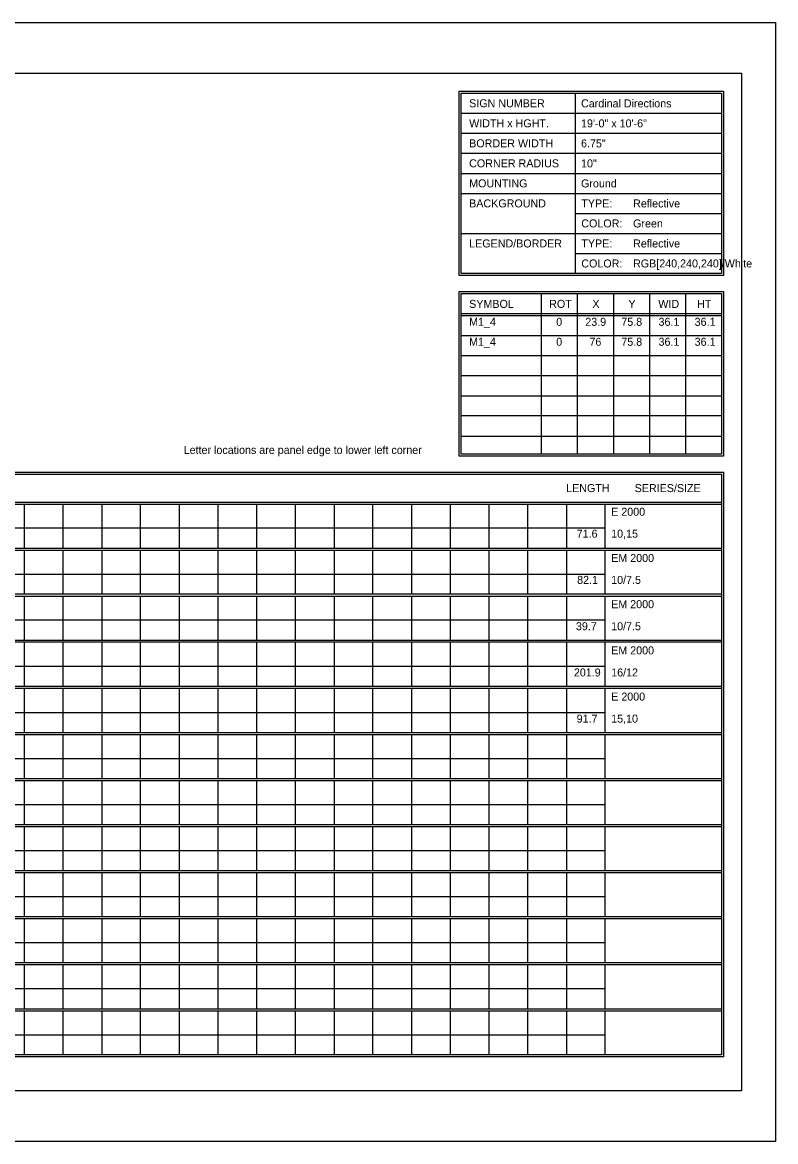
# Model space of a CAD drawing. Extents: x 1806251 to 1809821, y 414895 to 422886.
# Drawn here: x 1809679.34 to 1809684.89, y 414975.97 to 414984.23 of the extents above; entities that cross this region are included whole.
import ezdxf

# ---------------------------------------------------------------- set-up
doc = ezdxf.new("R2010")
doc.units = 0
doc.layers.add('GSSHT', color=7, linetype='Continuous')

msp = doc.modelspace()

# ---------------------------------------------------------------- linework, layer by layer
at = {"layer": 'GSSHT'}
for p, q in [((1809672.1343, 414984.2267), (1809684.8885, 414984.2267)), ((1809684.8885, 414984.2267), (1809684.8885, 414975.9729)), ((1809683.412, 414983.704), (1809683.412, 414982.3751)), ((1809682.5704, 414983.5563), (1809684.4899, 414983.5563)), ((1809682.5704, 414983.4087), (1809684.4899, 414983.4087)), ((1809682.5704, 414983.261), (1809684.4899, 414983.261)), ((1809682.5704, 414983.1134), (1809684.4899, 414983.1134)), ((1809682.5704, 414982.9657), (1809684.4899, 414982.9657)), ((1809683.412, 414982.8181), (1809684.4899, 414982.8181)), ((1809682.5704, 414982.6704), (1809684.4899, 414982.6704)), ((1809683.412, 414982.5227), (1809684.4899, 414982.5227)), ((1809683.161, 414982.2274), (1809683.161, 414981.0433)), ((1809683.4268, 414982.2274), (1809683.4268, 414981.0433)), ((1809683.6926, 414982.2274), (1809683.6926, 414981.0433)), ((1809683.9583, 414982.2274), (1809683.9583, 414981.0433)), ((1809684.2241, 414982.2274), (1809684.2241, 414981.0433)), ((1809682.5704, 414982.0798), (1809684.4899, 414982.0798)), ((1809682.5704, 414982.065), (1809684.4899, 414982.065)), ((1809682.5704, 414981.9174), (1809684.4899, 414981.9174)), ((1809682.5704, 414981.7697), (1809684.4899, 414981.7697)), ((1809682.5704, 414981.6221), (1809684.4899, 414981.6221)), ((1809682.5704, 414981.4715), (1809684.4899, 414981.4715)), ((1809682.5704, 414981.3268), (1809684.4899, 414981.3268)), ((1809682.5704, 414981.1762), (1809684.4899, 414981.1762)), ((1809672.781, 414980.6889), (1809684.4899, 414980.6889)), ((1809672.781, 414980.6741), (1809684.4899, 414980.6741)), ((1809679.3486, 414980.6741), (1809679.3486, 414980.3493)), ((1809679.6351, 414980.6741), (1809679.6351, 414980.3493)), ((1809679.9215, 414980.6741), (1809679.9215, 414980.3493)), ((1809680.205, 414980.6741), (1809680.205, 414980.3493)), ((1809680.4914, 414980.6741), (1809680.4914, 414980.3493)), ((1809680.7779, 414980.6741), (1809680.7779, 414980.3493)), ((1809681.0614, 414980.6741), (1809681.0614, 414980.3493)), ((1809681.3478, 414980.6741), (1809681.3478, 414980.3493)), ((1809681.6343, 414980.6741), (1809681.6343, 414980.3493)), ((1809681.9178, 414980.6741), (1809681.9178, 414980.3493)), ((1809682.2042, 414980.6741), (1809682.2042, 414980.3493)), ((1809682.4907, 414980.6741), (1809682.4907, 414980.3493)), ((1809682.7742, 414980.6741), (1809682.7742, 414980.3493)), ((1809683.0606, 414980.6741), (1809683.0606, 414980.3493)), ((1809683.347, 414980.6741), (1809683.347, 414980.3493)), ((1809683.6305, 414980.6741), (1809683.6305, 414980.3493)), ((1809672.781, 414980.4999), (1809683.6305, 414980.4999)), ((1809672.781, 414980.3493), (1809684.4899, 414980.3493)), ((1809672.781, 414980.3345), (1809684.4899, 414980.3345)), ((1809679.3486, 414980.3345), (1809679.3486, 414980.0127)), ((1809679.6351, 414980.3345), (1809679.6351, 414980.0127)), ((1809679.9215, 414980.3345), (1809679.9215, 414980.0127)), ((1809680.205, 414980.3345), (1809680.205, 414980.0127)), ((1809680.4914, 414980.3345), (1809680.4914, 414980.0127)), ((1809680.7779, 414980.3345), (1809680.7779, 414980.0127)), ((1809681.0614, 414980.3345), (1809681.0614, 414980.0127)), ((1809681.3478, 414980.3345), (1809681.3478, 414980.0127)), ((1809681.6343, 414980.3345), (1809681.6343, 414980.0127)), ((1809681.9178, 414980.3345), (1809681.9178, 414980.0127)), ((1809682.2042, 414980.3345), (1809682.2042, 414980.0127)), ((1809682.4907, 414980.3345), (1809682.4907, 414980.0127)), ((1809682.7742, 414980.3345), (1809682.7742, 414980.0127)), ((1809683.0606, 414980.3345), (1809683.0606, 414980.0127)), ((1809683.347, 414980.3345), (1809683.347, 414980.0127)), ((1809683.6305, 414980.3345), (1809683.6305, 414980.0127)), ((1809672.781, 414980.1574), (1809683.6305, 414980.1574)), ((1809672.781, 414980.0127), (1809684.4899, 414980.0127)), ((1809672.781, 414979.9949), (1809684.4899, 414979.9949)), ((1809679.3486, 414979.9949), (1809679.3486, 414979.6701)), ((1809679.6351, 414979.9949), (1809679.6351, 414979.6701)), ((1809679.9215, 414979.9949), (1809679.9215, 414979.6701)), ((1809680.205, 414979.9949), (1809680.205, 414979.6701)), ((1809680.4914, 414979.9949), (1809680.4914, 414979.6701)), ((1809680.7779, 414979.9949), (1809680.7779, 414979.6701)), ((1809681.0614, 414979.9949), (1809681.0614, 414979.6701)), ((1809681.3478, 414979.9949), (1809681.3478, 414979.6701)), ((1809681.6343, 414979.9949), (1809681.6343, 414979.6701)), ((1809681.9178, 414979.9949), (1809681.9178, 414979.6701)), ((1809682.2042, 414979.9949), (1809682.2042, 414979.6701)), ((1809682.4907, 414979.9949), (1809682.4907, 414979.6701)), ((1809682.7742, 414979.9949), (1809682.7742, 414979.6701)), ((1809683.0606, 414979.9949), (1809683.0606, 414979.6701)), ((1809683.347, 414979.9949), (1809683.347, 414979.6701)), ((1809683.6305, 414979.9949), (1809683.6305, 414979.6701)), ((1809672.781, 414979.8207), (1809683.6305, 414979.8207)), ((1809672.781, 414979.6701), (1809684.4899, 414979.6701)), ((1809672.781, 414979.6583), (1809684.4899, 414979.6583)), ((1809679.3486, 414979.6583), (1809679.3486, 414979.3305)), ((1809679.6351, 414979.6583), (1809679.6351, 414979.3305)), ((1809679.9215, 414979.6583), (1809679.9215, 414979.3305)), ((1809680.205, 414979.6583), (1809680.205, 414979.3305)), ((1809680.4914, 414979.6583), (1809680.4914, 414979.3305)), ((1809680.7779, 414979.6583), (1809680.7779, 414979.3305)), ((1809681.0614, 414979.6583), (1809681.0614, 414979.3305)), ((1809681.3478, 414979.6583), (1809681.3478, 414979.3305)), ((1809681.6343, 414979.6583), (1809681.6343, 414979.3305)), ((1809681.9178, 414979.6583), (1809681.9178, 414979.3305)), ((1809682.2042, 414979.6583), (1809682.2042, 414979.3305)), ((1809682.4907, 414979.6583), (1809682.4907, 414979.3305)), ((1809682.7742, 414979.6583), (1809682.7742, 414979.3305)), ((1809683.0606, 414979.6583), (1809683.0606, 414979.3305)), ((1809683.347, 414979.6583), (1809683.347, 414979.3305)), ((1809683.6305, 414979.6583), (1809683.6305, 414979.3305)), ((1809672.781, 414979.4782), (1809683.6305, 414979.4782)), ((1809672.781, 414979.3305), (1809684.4899, 414979.3305)), ((1809672.781, 414979.3157), (1809684.4899, 414979.3157)), ((1809679.3486, 414979.3157), (1809679.3486, 414978.9909)), ((1809679.6351, 414979.3157), (1809679.6351, 414978.9909)), ((1809679.9215, 414979.3157), (1809679.9215, 414978.9909)), ((1809680.205, 414979.3157), (1809680.205, 414978.9909)), ((1809680.4914, 414979.3157), (1809680.4914, 414978.9909)), ((1809680.7779, 414979.3157), (1809680.7779, 414978.9909)), ((1809681.0614, 414979.3157), (1809681.0614, 414978.9909)), ((1809681.3478, 414979.3157), (1809681.3478, 414978.9909)), ((1809681.6343, 414979.3157), (1809681.6343, 414978.9909)), ((1809681.9178, 414979.3157), (1809681.9178, 414978.9909)), ((1809682.2042, 414979.3157), (1809682.2042, 414978.9909)), ((1809682.4907, 414979.3157), (1809682.4907, 414978.9909)), ((1809682.7742, 414979.3157), (1809682.7742, 414978.9909)), ((1809683.0606, 414979.3157), (1809683.0606, 414978.9909)), ((1809683.347, 414979.3157), (1809683.347, 414978.9909)), ((1809683.6305, 414979.3157), (1809683.6305, 414978.9909)), ((1809672.781, 414979.1385), (1809683.6305, 414979.1385)), ((1809672.781, 414978.9909), (1809684.4899, 414978.9909)), ((1809672.781, 414978.9761), (1809684.4899, 414978.9761)), ((1809679.3486, 414978.9761), (1809679.3486, 414978.6513)), ((1809679.6351, 414978.9761), (1809679.6351, 414978.6513)), ((1809679.9215, 414978.9761), (1809679.9215, 414978.6513)), ((1809680.205, 414978.9761), (1809680.205, 414978.6513)), ((1809680.4914, 414978.9761), (1809680.4914, 414978.6513)), ((1809680.7779, 414978.9761), (1809680.7779, 414978.6513)), ((1809681.0614, 414978.9761), (1809681.0614, 414978.6513)), ((1809681.3478, 414978.9761), (1809681.3478, 414978.6513)), ((1809681.6343, 414978.9761), (1809681.6343, 414978.6513)), ((1809681.9178, 414978.9761), (1809681.9178, 414978.6513)), ((1809682.2042, 414978.9761), (1809682.2042, 414978.6513)), ((1809682.4907, 414978.9761), (1809682.4907, 414978.6513)), ((1809682.7742, 414978.9761), (1809682.7742, 414978.6513)), ((1809683.0606, 414978.9761), (1809683.0606, 414978.6513)), ((1809683.347, 414978.9761), (1809683.347, 414978.6513)), ((1809683.6305, 414978.9761), (1809683.6305, 414978.6513)), ((1809672.781, 414978.7989), (1809683.6305, 414978.7989)), ((1809672.781, 414978.6513), (1809684.4899, 414978.6513)), ((1809672.781, 414978.6365), (1809684.4899, 414978.6365)), ((1809679.3486, 414978.6365), (1809679.3486, 414978.3117)), ((1809679.6351, 414978.6365), (1809679.6351, 414978.3117)), ((1809679.9215, 414978.6365), (1809679.9215, 414978.3117)), ((1809680.205, 414978.6365), (1809680.205, 414978.3117)), ((1809680.4914, 414978.6365), (1809680.4914, 414978.3117)), ((1809680.7779, 414978.6365), (1809680.7779, 414978.3117)), ((1809681.0614, 414978.6365), (1809681.0614, 414978.3117)), ((1809681.3478, 414978.6365), (1809681.3478, 414978.3117)), ((1809681.6343, 414978.6365), (1809681.6343, 414978.3117)), ((1809681.9178, 414978.6365), (1809681.9178, 414978.3117)), ((1809682.2042, 414978.6365), (1809682.2042, 414978.3117)), ((1809682.4907, 414978.6365), (1809682.4907, 414978.3117)), ((1809682.7742, 414978.6365), (1809682.7742, 414978.3117)), ((1809683.0606, 414978.6365), (1809683.0606, 414978.3117)), ((1809683.347, 414978.6365), (1809683.347, 414978.3117)), ((1809683.6305, 414978.6365), (1809683.6305, 414978.3117)), ((1809672.781, 414978.4593), (1809683.6305, 414978.4593)), ((1809672.781, 414978.3117), (1809684.4899, 414978.3117)), ((1809672.781, 414978.2969), (1809684.4899, 414978.2969)), ((1809679.3486, 414978.2969), (1809679.3486, 414977.9721)), ((1809679.6351, 414978.2969), (1809679.6351, 414977.9721)), ((1809679.9215, 414978.2969), (1809679.9215, 414977.9721)), ((1809680.205, 414978.2969), (1809680.205, 414977.9721)), ((1809680.4914, 414978.2969), (1809680.4914, 414977.9721)), ((1809680.7779, 414978.2969), (1809680.7779, 414977.9721)), ((1809681.0614, 414978.2969), (1809681.0614, 414977.9721)), ((1809681.3478, 414978.2969), (1809681.3478, 414977.9721)), ((1809681.6343, 414978.2969), (1809681.6343, 414977.9721)), ((1809681.9178, 414978.2969), (1809681.9178, 414977.9721)), ((1809682.2042, 414978.2969), (1809682.2042, 414977.9721)), ((1809682.4907, 414978.2969), (1809682.4907, 414977.9721)), ((1809682.7742, 414978.2969), (1809682.7742, 414977.9721)), ((1809683.0606, 414978.2969), (1809683.0606, 414977.9721)), ((1809683.347, 414978.2969), (1809683.347, 414977.9721)), ((1809683.6305, 414978.2969), (1809683.6305, 414977.9721)), ((1809672.781, 414978.1197), (1809683.6305, 414978.1197)), ((1809672.781, 414977.9721), (1809684.4899, 414977.9721)), ((1809672.781, 414977.9573), (1809684.4899, 414977.9573)), ((1809679.3486, 414977.9573), (1809679.3486, 414977.6325)), ((1809679.6351, 414977.9573), (1809679.6351, 414977.6325)), ((1809679.9215, 414977.9573), (1809679.9215, 414977.6325)), ((1809680.205, 414977.9573), (1809680.205, 414977.6325)), ((1809680.4914, 414977.9573), (1809680.4914, 414977.6325)), ((1809680.7779, 414977.9573), (1809680.7779, 414977.6325)), ((1809681.0614, 414977.9573), (1809681.0614, 414977.6325)), ((1809681.3478, 414977.9573), (1809681.3478, 414977.6325)), ((1809681.6343, 414977.9573), (1809681.6343, 414977.6325)), ((1809681.9178, 414977.9573), (1809681.9178, 414977.6325)), ((1809682.2042, 414977.9573), (1809682.2042, 414977.6325)), ((1809682.4907, 414977.9573), (1809682.4907, 414977.6325)), ((1809682.7742, 414977.9573), (1809682.7742, 414977.6325)), ((1809683.0606, 414977.9573), (1809683.0606, 414977.6325)), ((1809683.347, 414977.9573), (1809683.347, 414977.6325)), ((1809683.6305, 414977.9573), (1809683.6305, 414977.6325)), ((1809672.781, 414977.7801), (1809683.6305, 414977.7801)), ((1809672.781, 414977.6325), (1809684.4899, 414977.6325)), ((1809672.781, 414977.6177), (1809684.4899, 414977.6177)), ((1809679.3486, 414977.6177), (1809679.3486, 414977.2929)), ((1809679.6351, 414977.6177), (1809679.6351, 414977.2929)), ((1809679.9215, 414977.6177), (1809679.9215, 414977.2929)), ((1809680.205, 414977.6177), (1809680.205, 414977.2929)), ((1809680.4914, 414977.6177), (1809680.4914, 414977.2929)), ((1809680.7779, 414977.6177), (1809680.7779, 414977.2929)), ((1809681.0614, 414977.6177), (1809681.0614, 414977.2929)), ((1809681.3478, 414977.6177), (1809681.3478, 414977.2929)), ((1809681.6343, 414977.6177), (1809681.6343, 414977.2929)), ((1809681.9178, 414977.6177), (1809681.9178, 414977.2929)), ((1809682.2042, 414977.6177), (1809682.2042, 414977.2929)), ((1809682.4907, 414977.6177), (1809682.4907, 414977.2929)), ((1809682.7742, 414977.6177), (1809682.7742, 414977.2929)), ((1809683.0606, 414977.6177), (1809683.0606, 414977.2929)), ((1809683.347, 414977.6177), (1809683.347, 414977.2929)), ((1809683.6305, 414977.6177), (1809683.6305, 414977.2929)), ((1809672.781, 414977.4405), (1809683.6305, 414977.4405)), ((1809672.781, 414977.2929), (1809684.4899, 414977.2929)), ((1809672.781, 414977.2781), (1809684.4899, 414977.2781)), ((1809679.3486, 414977.2781), (1809679.3486, 414976.9533)), ((1809679.6351, 414977.2781), (1809679.6351, 414976.9533)), ((1809679.9215, 414977.2781), (1809679.9215, 414976.9533)), ((1809680.205, 414977.2781), (1809680.205, 414976.9533)), ((1809680.4914, 414977.2781), (1809680.4914, 414976.9533)), ((1809680.7779, 414977.2781), (1809680.7779, 414976.9533)), ((1809681.0614, 414977.2781), (1809681.0614, 414976.9533)), ((1809681.3478, 414977.2781), (1809681.3478, 414976.9533)), ((1809681.6343, 414977.2781), (1809681.6343, 414976.9533)), ((1809681.9178, 414977.2781), (1809681.9178, 414976.9533)), ((1809682.2042, 414977.2781), (1809682.2042, 414976.9533)), ((1809682.4907, 414977.2781), (1809682.4907, 414976.9533)), ((1809682.7742, 414977.2781), (1809682.7742, 414976.9533)), ((1809683.0606, 414977.2781), (1809683.0606, 414976.9533)), ((1809683.347, 414977.2781), (1809683.347, 414976.9533)), ((1809683.6305, 414977.2781), (1809683.6305, 414976.9533)), ((1809672.781, 414977.1009), (1809683.6305, 414977.1009)), ((1809672.781, 414976.9533), (1809684.4899, 414976.9533)), ((1809672.781, 414976.9385), (1809684.4899, 414976.9385)), ((1809679.3486, 414976.9385), (1809679.3486, 414976.6137)), ((1809679.6351, 414976.9385), (1809679.6351, 414976.6137)), ((1809679.9215, 414976.9385), (1809679.9215, 414976.6137)), ((1809680.205, 414976.9385), (1809680.205, 414976.6137)), ((1809680.4914, 414976.9385), (1809680.4914, 414976.6137)), ((1809680.7779, 414976.9385), (1809680.7779, 414976.6137)), ((1809681.0614, 414976.9385), (1809681.0614, 414976.6137)), ((1809681.3478, 414976.9385), (1809681.3478, 414976.6137)), ((1809681.6343, 414976.9385), (1809681.6343, 414976.6137)), ((1809681.9178, 414976.9385), (1809681.9178, 414976.6137)), ((1809682.2042, 414976.9385), (1809682.2042, 414976.6137)), ((1809682.4907, 414976.9385), (1809682.4907, 414976.6137)), ((1809682.7742, 414976.9385), (1809682.7742, 414976.6137)), ((1809683.0606, 414976.9385), (1809683.0606, 414976.6137)), ((1809683.347, 414976.9385), (1809683.347, 414976.6137)), ((1809683.6305, 414976.9385), (1809683.6305, 414976.6137)), ((1809672.781, 414976.7613), (1809683.6305, 414976.7613)), ((1809684.8885, 414975.9729), (1809672.1343, 414975.9729))]:
    msp.add_line(p, q, dxfattribs=at)
for points in [[(1809672.6334, 414983.8516), (1809684.6375, 414983.8516), (1809684.6375, 414976.3479), (1809672.6334, 414976.3479)], [(1809682.5556, 414983.7187), (1809684.5046, 414983.7187), (1809684.5046, 414982.3603), (1809682.5556, 414982.3603)], [(1809682.5704, 414983.704), (1809684.4899, 414983.704), (1809684.4899, 414982.3751), (1809682.5704, 414982.3751)], [(1809682.5556, 414982.2422), (1809684.5046, 414982.2422), (1809684.5046, 414981.0285), (1809682.5556, 414981.0285)], [(1809682.5704, 414982.2274), (1809684.4899, 414982.2274), (1809684.4899, 414981.0433), (1809682.5704, 414981.0433)], [(1809672.7663, 414980.9104), (1809684.5046, 414980.9104), (1809684.5046, 414976.5989), (1809672.7663, 414976.5989)], [(1809672.781, 414980.8956), (1809684.4899, 414980.8956), (1809684.4899, 414976.6137), (1809672.781, 414976.6137)]]:
    msp.add_lwpolyline(points, close=True, dxfattribs=at)

# ---------------------------------------------------------------- texts
for s, height, p in [('SIGN NUMBER', 0.059055, (1809682.6295, 414983.6006)), ('Cardinal Directions', 0.059025, (1809683.4543, 414983.5999)), ('WIDTH x HGHT.', 0.059055, (1809682.6295, 414983.453)), ('19\'-0" x 10\'-6"', 0.059025, (1809683.4543, 414983.4523)), ('BORDER WIDTH', 0.059055, (1809682.6295, 414983.3053)), ('6.75"', 0.05903, (1809683.4543, 414983.3047)), ('CORNER RADIUS', 0.059055, (1809682.6295, 414983.1577)), ('10"', 0.05903, (1809683.4543, 414983.1572)), ('MOUNTING', 0.05906, (1809682.6295, 414983.01)), ('Ground', 0.05903, (1809683.4543, 414983.0096)), ('BACKGROUND', 0.05906, (1809682.6295, 414982.8623)), ('TYPE:', 0.05906, (1809683.4563, 414982.8623)), ('Reflective', 0.05903, (1809683.838, 414982.8621)), ('COLOR:', 0.05906, (1809683.4563, 414982.7147)), ('Green', 0.05903, (1809683.838, 414982.7145)), ('LEGEND/BORDER', 0.059055, (1809682.6295, 414982.567)), ('TYPE:', 0.05906, (1809683.4563, 414982.567)), ('Reflective', 0.05903, (1809683.838, 414982.5669)), ('COLOR:', 0.05906, (1809683.4563, 414982.4194)), ('RGB[240,240,240]/White', 0.059025, (1809683.838, 414982.4194)), ('SYMBOL', 0.05906, (1809682.6295, 414982.1211)), ('ROT', 0.05906, (1809683.2194, 414982.1211)), ('X', 0.0591, (1809683.5374, 414982.1211)), ('Y', 0.0591, (1809683.8035, 414982.1211)), ('WID', 0.05906, (1809684.024, 414982.1211)), ('HT', 0.05906, (1809684.3096, 414982.1211)), ('M1_4', 0.05903, (1809682.629, 414981.9889)), ('0', 0.059, (1809683.2714, 414981.9889)), ('23.9', 0.05903, (1809683.4856, 414981.9889)), ('75.8', 0.05903, (1809683.7513, 414981.9889)), ('36.1', 0.05903, (1809684.0256, 414981.9889)), ('36.1', 0.05903, (1809684.2917, 414981.9889)), ('M1_4', 0.05903, (1809682.629, 414981.8418)), ('0', 0.059, (1809683.2714, 414981.8418)), ('76', 0.05903, (1809683.5161, 414981.8418)), ('75.8', 0.05903, (1809683.7513, 414981.8418)), ('36.1', 0.05903, (1809684.0256, 414981.8418)), ('36.1', 0.05903, (1809684.2917, 414981.8418)), ('Letter locations are panel edge to lower left corner', 0.059025, (1809680.5251, 414981.0441)), ('LENGTH', 0.05906, (1809683.3444, 414980.7627)), ('SERIES/SIZE', 0.059061, (1809683.8496, 414980.7627)), ('E 2000', 0.05903, (1809683.6765, 414980.5882)), ('71.6', 0.05903, (1809683.4221, 414980.4265)), ('10,15', 0.05903, (1809683.6765, 414980.4265)), ('EM 2000', 0.05903, (1809683.6765, 414980.2474)), ('82.1', 0.05903, (1809683.4256, 414980.0858)), ('10/7.5', 0.05903, (1809683.6765, 414980.0858)), ('EM 2000', 0.05903, (1809683.6765, 414979.9067)), ('39.7', 0.05903, (1809683.4166, 414979.7441)), ('10/7.5', 0.05903, (1809683.6765, 414979.7441)), ('EM 2000', 0.05903, (1809683.6765, 414979.566)), ('201.9', 0.05903, (1809683.4016, 414979.4033)), ('16/12', 0.05903, (1809683.6765, 414979.4033)), ('E 2000', 0.05903, (1809683.6765, 414979.2252)), ('91.7', 0.05903, (1809683.4221, 414979.0626)), ('15,10', 0.05903, (1809683.6765, 414979.0626))]:
    msp.add_text(s, height=height, dxfattribs=at).set_placement(p)

doc.saveas('drawing.dxf')
